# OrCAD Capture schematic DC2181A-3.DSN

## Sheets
1 PAGE 2: size Custom; title: BAR GRAPH FOR 400mA WIRELESS SYNCHRONOUS; rev: 3; note: DEMO CIRCUIT 2181A - A / B
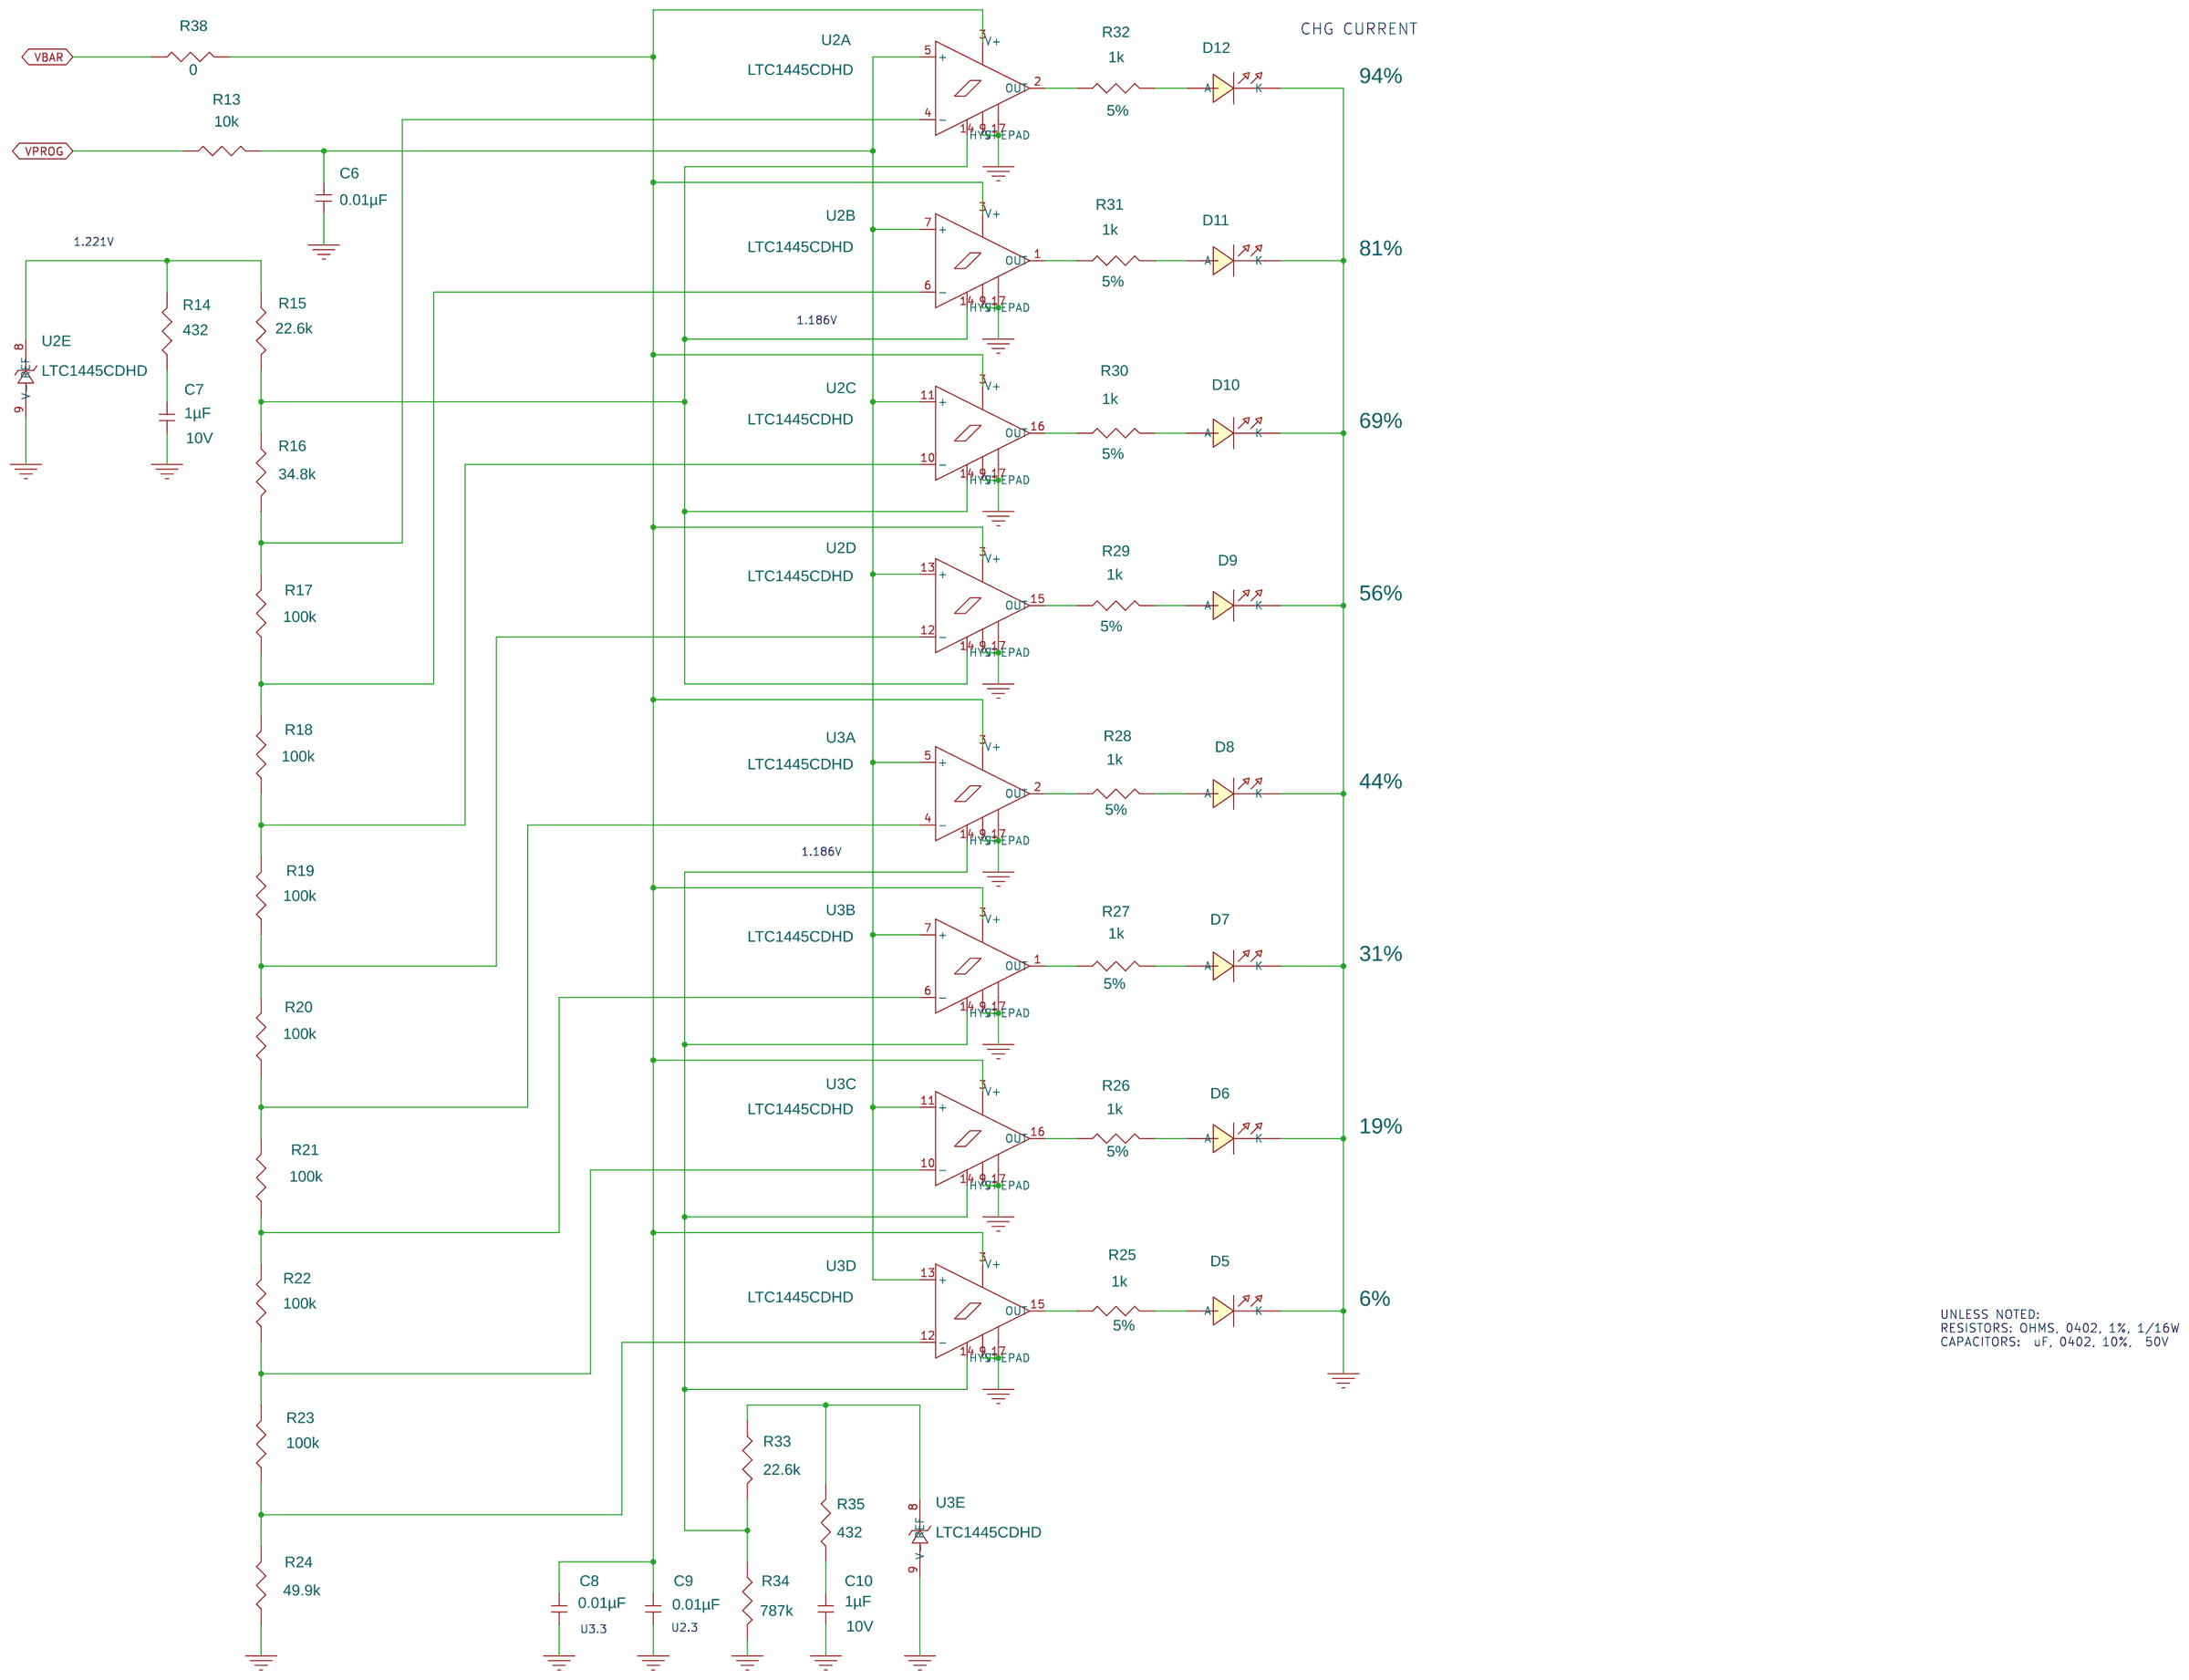
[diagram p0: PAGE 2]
2 PAGE 1: size A; title: 400mA WIRELESS SYNCHRONOUS BUCK BATTERY CHARGER
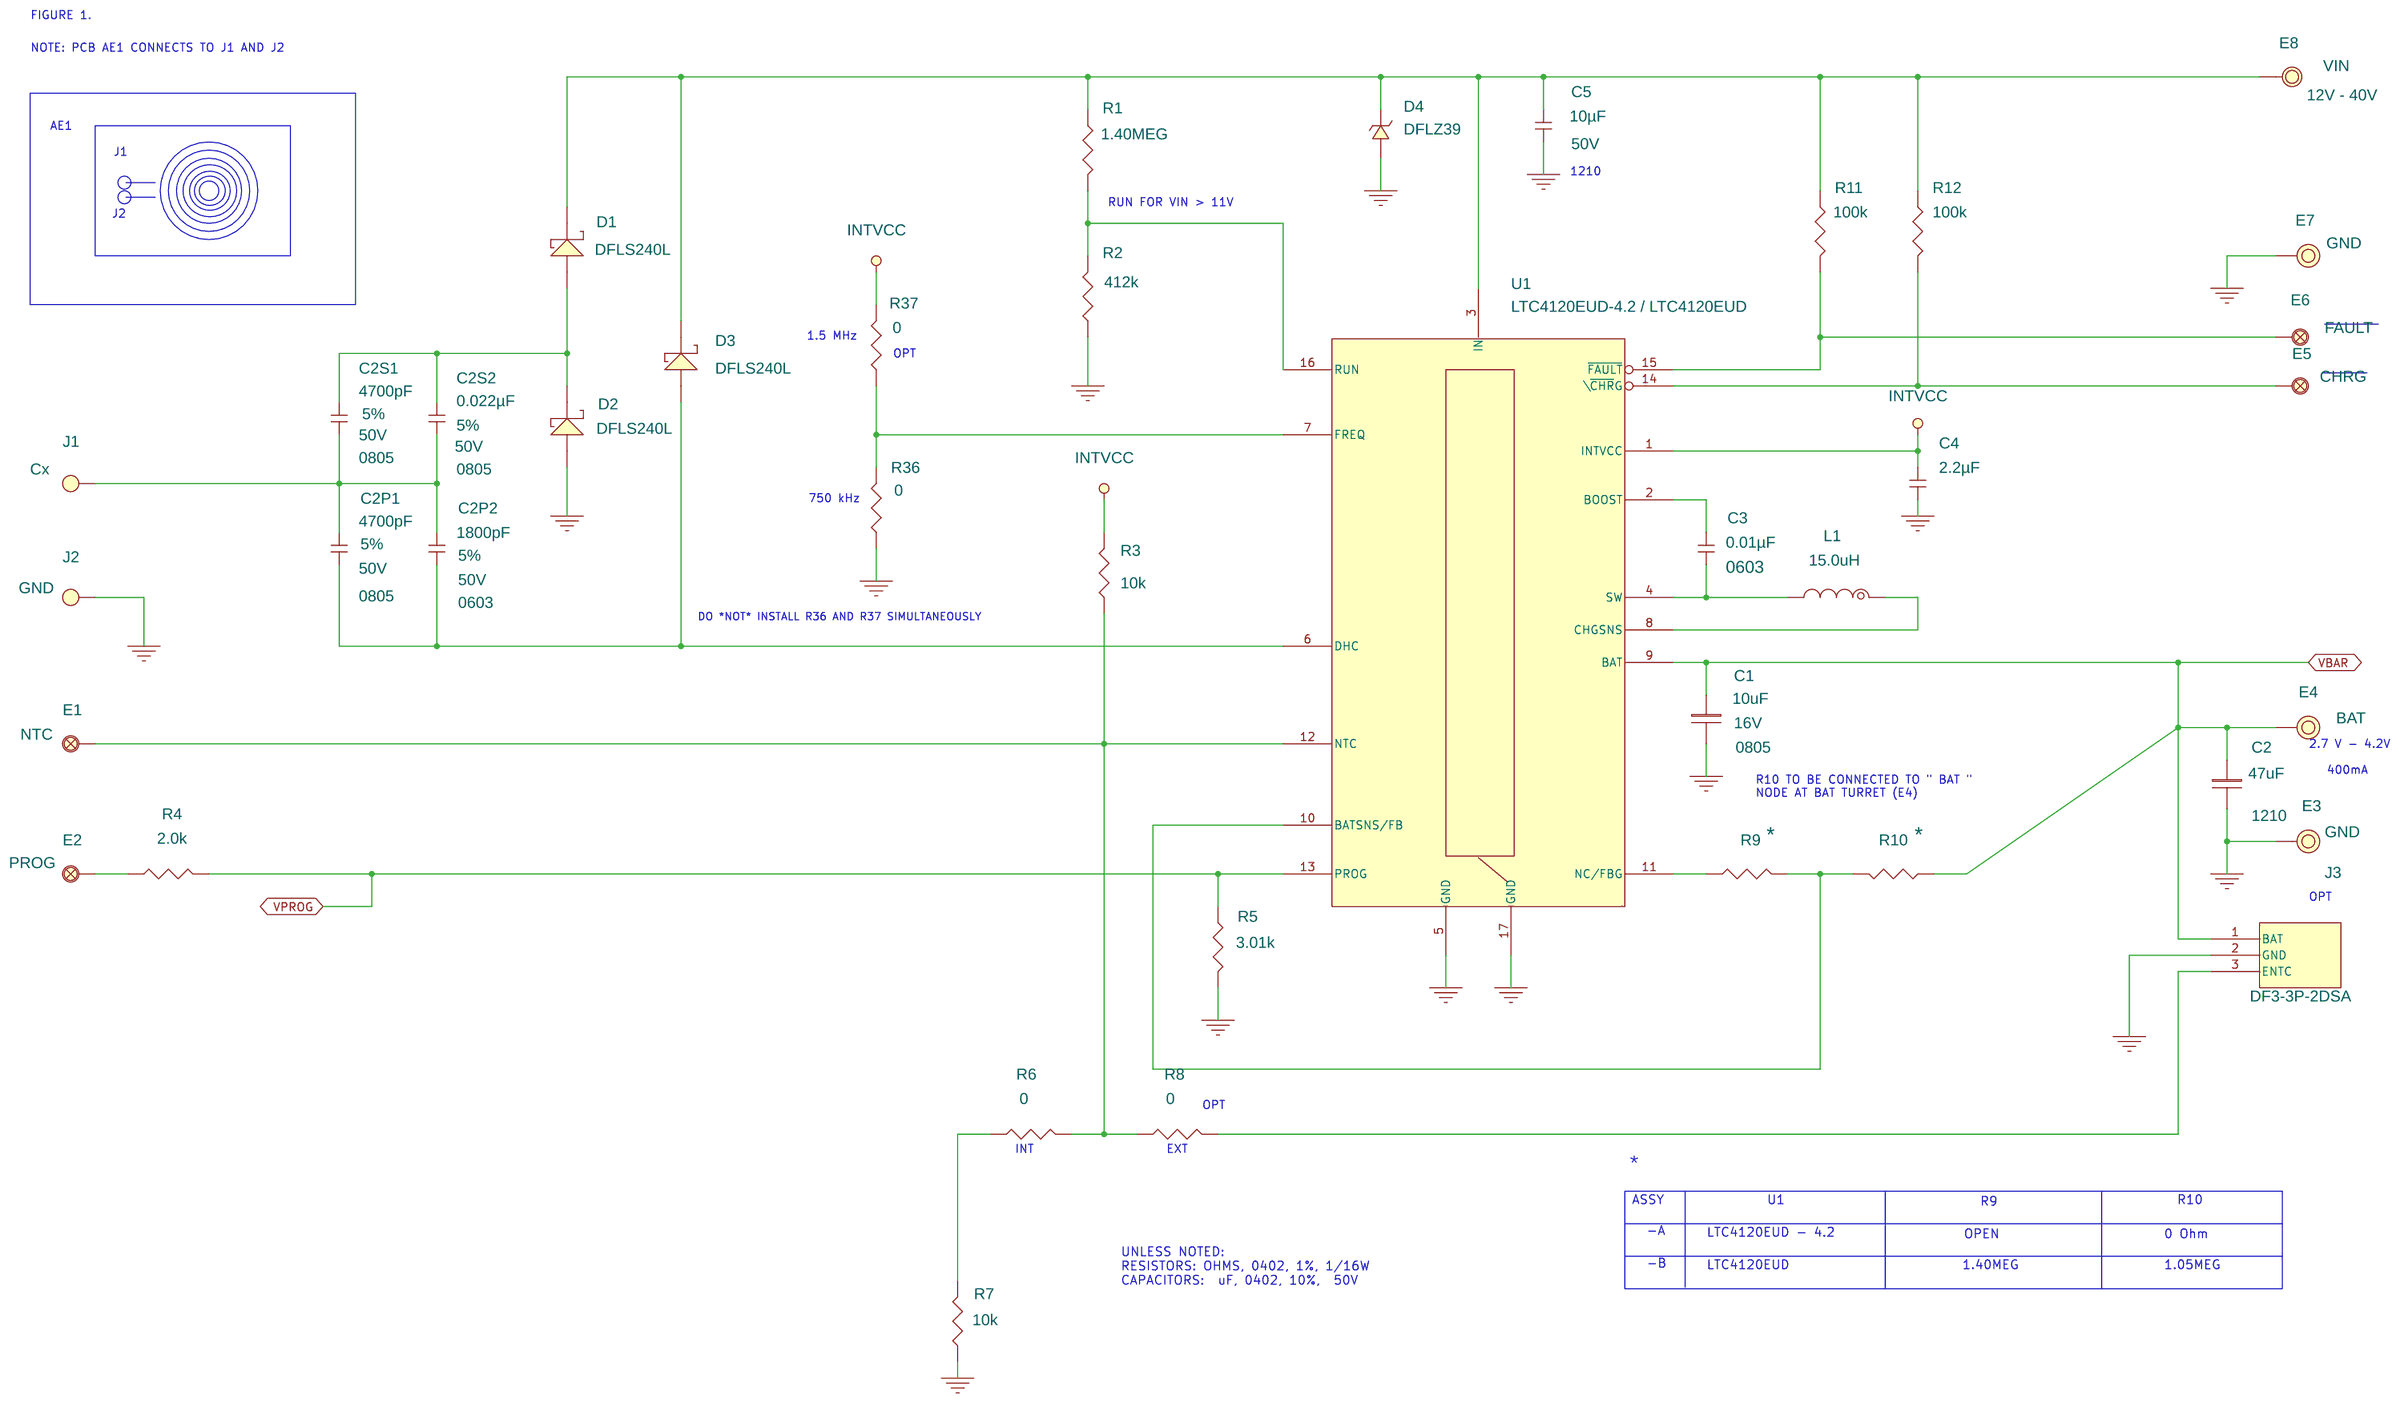
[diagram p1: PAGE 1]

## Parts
sheet PAGE 1
C1  10uF  [0805]
C2  47uF  [1210]
C2P1  4700pF  [0805]
C2P2  1800pF  [0603]
C2S1  4700pF  [0805]
C2S2  0.022µF  [0805]
C3  0.01µF  [0603]
C4  2.2µF  [0402-SMALL]
C5  10µF  [1210]
D1  DFLS240L  [POWERDI123A]
D2  DFLS240L  [POWERDI123A]
D3  DFLS240L  [POWERDI123A]
D4  DFLZ39  [POWERDI123A]
E1  NTC  [MILL-MAX-2308]
E2  PROG  [MILL-MAX-2308]
E3  GND  [MILL-MAX-2501-2]
E4  BAT  [MILL-MAX-2501-2]
E5  CHRG  [MILL-MAX-2308]
E6  FAULT  [MILL-MAX-2308]
E7  GND  [MILL-MAX-2501-2]
E8  VIN  [MILL-MAX-2501-2]
J1  Cx  [PAD060/024]
J2  GND  [PAD060/024]
J3  DF3-3P-2DSA  [DF32DSHEADER]
L1  15.0uH  [LPS4018]
R1  1.40MEG  [0402-SMALL]
R2  412k  [0402-SMALL]
R3  10k  [0402-SMALL]
R4  2.0k  [0402-SMALL]
R5  3.01k  [0402-SMALL]
R6  0  [0402-SMALL]
R7  10k  [0402-SMALL]
R8  0  [0402-SMALL]
R9  *  [0402-SMALL]
R10  *  [0402-SMALL]
R11  100k  [0402-SMALL]
R12  100k  [0402-SMALL]
R36  0  [0402-SMALL]
R37  0  [0402-SMALL]
U1  LTC4120EUD-4.2 / LTC4120EUD  [QFN(16)(UD)3MMX3MM]
sheet PAGE 2
C6  0.01µF  [0402-SMALL]
C7  1µF  [0402-SMALL]
C8  0.01µF  [0402-SMALL]
C9  0.01µF  [0402-SMALL]
C10  1µF  [0402-SMALL]
D5  6%  [LITE-ON-GREEN-LED]
D6  19%  [LITE-ON-GREEN-LED]
D7  31%  [LITE-ON-GREEN-LED]
D8  44%  [LITE-ON-GREEN-LED]
D9  56%  [LITE-ON-GREEN-LED]
D10  69%  [LITE-ON-GREEN-LED]
D11  81%  [LITE-ON-GREEN-LED]
D12  94%  [LITE-ON-GREEN-LED]
R13  10k  [0402-SMALL]
R14  432  [0402-SMALL]
R15  22.6k  [0402-SMALL]
R16  34.8k  [0402-SMALL]
R17  100k  [0402-SMALL]
R18  100k  [0402-SMALL]
R19  100k  [0402-SMALL]
R20  100k  [0402-SMALL]
R21  100k  [0402-SMALL]
R22  100k  [0402-SMALL]
R23  100k  [0402-SMALL]
R24  49.9k  [0402-SMALL]
R25  1k  [0402-SMALL]
R26  1k  [0402-SMALL]
R27  1k  [0402-SMALL]
R28  1k  [0402-SMALL]
R29  1k  [0402-SMALL]
R30  1k  [0402-SMALL]
R31  1k  [0402-SMALL]
R32  1k  [0402-SMALL]
R33  22.6k  [0402-SMALL]
R34  787k  [0402-SMALL]
R35  432  [0402-SMALL]
R38  0  [0402-SMALL]
U2  LTC1445CDHD  [DFN(16)(DHD)5MMX4MM]  (sections A,B,C,D,E)
U3  LTC1445CDHD  [DFN(16)(DHD)5MMX4MM]  (sections A,B,C,D,E)

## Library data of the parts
C1 = C2012X5R1A106K: VOLTAGE: 16V
C2 = GRM32ER61C476KE15L
C2P1 C2S1 = GRM31CR61E106KA12L_0: PART: GRM2165C1H472JA01D; Tolerance: 5%; VOLTAGE: 50V
C2P2 = GRM31CR61E106KA12L_0: PART: C0603C182J5GACTU; Tolerance: 5%; VOLTAGE: 50V
C2S2 = GRM31CR61E106KA12L_0: PART: GRM21B5C1H223JA01L; Tolerance: 5%; VOLTAGE: 50V
C3 = VJ0402Y103JXXA_0
C4 = GRM155R60J225ME15D_0
C5 = GRM31CR61E106KA12L_0: 6th Part Field: CL31A106KBHNNNB; VOLTAGE: 50V
D1-D3 = DFLS1100_0
D4 = DFLZ39
E1 E2 E5 E6 = TP_KEY_1502-2_0: 4th Part Field: MILL-MAX; 5th Part Field: 2308-2; 7th Part Field: TURRET, SIGNAL; 9th Part Field: EN1; Part Number: MILL-MAX 2308-2
E3 E7 = E_3
E4 = E_3: TURRET
E8 = MillMax-2501-2: 10th Part Field: VBUS; 4th Part Field: MILL-MAX; 9th Part Field: 12V - 40V
J1 J2 = T_POINT_R
J3 = CON3_1
L1 = LPS4018-153MLC
R1 = CRCW0402140KFKED
R2 R9 R10 R14 R17-R24 R35 R38 = CRCW0402100KFKED
R3 R36 R37 = CR16-103JM_0: 2nd Part Field: 0402; 3rd Part Field: CHIP; 4th Part Field: VISHAY; 5th Part Field: CRCW040210K0FKED; 7th Part Field: RES; Part Number: VISHAY CRCW0402 10K 1%; Tolerance: 1%
R4 R6 R8 R13 = CRCW04022K00JNED
R5 = CRCW04023K01FKED
R7 = CR16-103JM_0: 1st Part Field: 1/16W; 2nd Part Field: 0402; 3rd Part Field: CHIP; 4th Part Field: VISHAY; 5th Part Field: CRCW040210K0FKED; 7th Part Field: RES; Part Number: VISHAY CRCW0402 10k 1%; Tolerance: 1%
R11 R12 = CRCW0402100KJNED
U1 = 20LQFN(3X3)_93
C6 C8 C9 = GRM31CR61E106KA12L_0
C7 C10 = GRM31CR61E106KA12L_0: VOLTAGE: 10V
D5-D12 = ln1351-c-tr_1: 5th Part Field: LNJ336W83RA; 9th Part Field: SMT, GREEN; Part Number: LNJ336W83RA
R15 R33 = CRCW040222K6FKED
R16 = CRCW040227K4FKED
R25-R32 = CRCW0402100KFKED: Tolerance: 5%
R34 = CRCW0402787KFKED
U2 U3 = LTC1445CDHD_7

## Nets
GND: C1.2 C2.2 C4.2 C5.2 C6.2 C7.2 C8.2 C9.2 C10.2 D2.2(A) D4.2 D5.2(K) D6.2(K) D7.2(K) D8.2(K) D9.2(K) D10.2(K) D11.2(K) D12.2(K) E3.1(A) E7.1(A) J2.1(TP) J3.2(GND) R2.1(pin1) R5.2(pin2) R7.2 R24.1(pin1) R34.2(pin2) R36.2 U1.5(GND) U1.17(GND) U2.9(V-) U2.17(EPAD) U3.9(V-) U3.17(EPAD)
INTVCC: C4.1 R3.1 R37.1 U1.1(INTVCC)
VBAR: C1.1 C2.1 E4.1(A) J3.1(BAT) R10.1(pin1) R38.1(pin1) U1.9(BAT)
VPROG: R4.2(pin2) R5.1(pin1) R13.1(pin1) U1.13(PROG)
N17141032: R1.2(pin2) R2.2(pin2) U1.16(RUN)
N17195283: R6.1(pin1) R7.1
N17197391: J3.3(ENTC) R8.2(pin2)
N17301488: E1.1 R3.2 R6.2(pin2) R8.1(pin1) U1.12(NTC)
N17303729: C5.1 D1.1(C) D3.1(C) D4.1 E8.1 R1.1(pin1) R11.1(pin1) R12.1(pin1) U1.3(IN)
N17342929: C3.2 L1.2 U1.4(SW)
N17342957: L1.1 U1.8(CHGSNS)
N17343033: C3.1 U1.2(BOOST)
N17343389: E5.1 R12.2(pin2) U1.14(\~{CHR}G)
N17343421: E6.1 R11.2(pin2) U1.15(~{FAULT})
N17344705: R36.1 R37.2 U1.7(FREQ)
N17345301: E2.1 R4.1(pin1)
N17346791: C2P1.2 C2P2.2 D3.2(A) U1.6(DHC)
N17348130: C2P1.1 C2P2.1 C2S1.2 C2S2.2 J1.1(TP)
N17348152: C2S1.1 C2S2.1 D1.2(A) D2.1(C)
N17350124: R9.1(pin1) U1.11(NC/FBG)
N17352615: R9.2(pin2) R10.2(pin2) U1.10(BATSNS/FB)
N17379047: C6.1 R13.2(pin2) U2.5(+) U2.7(+) U2.11(+) U2.13(+) U3.5(+) U3.7(+) U3.11(+) U3.13(+)
N17387943: R33.2(pin2) R34.1(pin1) U3.14(HYST)
N17388008: R15.2(pin2) R16.1(pin1) U2.14(HYST)
N17388100: C8.1 C9.1 R38.2(pin2) U2.3(V+) U3.3(V+)
N17388523: R16.2(pin2) R17.2(pin2) U2.4(-)
N17388537: R17.1(pin1) R18.2(pin2) U2.6(-)
N17388551: R18.1(pin1) R19.2(pin2) U2.10(-)
N17388565: R19.1(pin1) R20.2(pin2) U2.12(-)
N17388579: R20.1(pin1) R21.2(pin2) U3.4(-)
N17388621: R23.1(pin1) R24.2(pin2) U3.12(-)
N17389104: R14.2(pin2) R15.1(pin1) U2.8(REF)
N17396884: R32.1(pin1) U2.2(OUT)
N17396885: R28.1(pin1) U3.2(OUT)
N17396886: R29.1(pin1) U2.15(OUT)
N17396887: R31.1(pin1) U2.1(OUT)
N17396889: R30.1(pin1) U2.16(OUT)
N17396890: R25.1(pin1) U3.15(OUT)
N17396891: R27.1(pin1) U3.1(OUT)
N17397508: R22.1(pin1) R23.2(pin2) U3.10(-)
N17397664: R21.1(pin1) R22.2(pin2) U3.6(-)
N17400203: C7.1 R14.1(pin1)
N17419772: D12.1(A) R32.2(pin2)
N17419787: D11.1(A) R31.2(pin2)
N17419802: D10.1(A) R30.2(pin2)
N17419817: D9.1(A) R29.2(pin2)
N17419832: D8.1(A) R28.2(pin2)
N17419847: D7.1(A) R27.2(pin2)
N17419862: D6.1(A) R26.2(pin2)
N17419877: D5.1(A) R25.2(pin2)
N17423487: R26.1(pin1) U3.16(OUT)
N17431016: R33.1(pin1) R35.2(pin2) U3.8(REF)
N17431455: C10.1 R35.1(pin1)

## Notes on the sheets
sheet 1
- CHG CURRENT
- 1.221V
- 1.186V
- 1.186V
- UNLESS NOTED:
  RESISTORS: OHMS, 0402, 1%, 1/16W
  CAPACITORS:  uF, 0402, 10%,  50V
- U3.3
- U2.3
sheet 2
- FIGURE 1.
- NOTE: PCB AE1 CONNECTS TO J1 AND J2
- AE1
- J1
- 1210
- RUN FOR VIN > 11V
- J2
- 1.5 MHz
- OPT
- 750 kHz
- DO *NOT* INSTALL R36 AND R37 SIMULTANEOUSLY
- 2.7 V - 4.2V
- R10 TO BE CONNECTED TO " BAT "
  NODE AT BAT TURRET (E4)
- 400mA
- OPT
- OPT
- INT
- EXT
- *
- ASSY
- U1
- R9
- R10
- -A
- LTC4120EUD - 4.2
- OPEN
- 0 Ohm
- UNLESS NOTED:
  RESISTORS: OHMS, 0402, 1%, 1/16W
  CAPACITORS:  uF, 0402, 10%,  50V
- -B
- LTC4120EUD
- 1.40MEG
- 1.05MEG
